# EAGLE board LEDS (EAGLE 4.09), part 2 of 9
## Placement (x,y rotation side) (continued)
LED12.81  LED_CROSS1/2  [LED_603]  33.11,22.47 180 top
LED12.82  LED_CROSS1/2  [LED_603]  34.92,22.47 180 top
LED12.83  LED_CROSS1/2  [LED_603]  36.72,22.47 180 top
LED12.84  LED_CROSS1/2  [LED_603]  38.53,22.47 180 top
LED12.85  LED_CROSS1/2  [LED_603]  40.33,22.47 180 top
LED12.86  LED_CROSS1/2  [LED_603]  42.12,22.47 180 top
LED12.87  LED_CROSS1/2  [LED_603]  43.92,22.47 180 top
LED12.88  LED_CROSS1/2  [LED_603]  45.71,22.47 180 top
LED12.89  LED_CROSS1/2  [LED_603]  47.5,22.47 180 top
LED12.90  LED_CROSS1/2  [LED_603]  49.3,22.47 180 top
LED12.91  LED_CROSS1/2  [LED_603]  51.12,22.47 180 top
LED12.92  LED_CROSS1/2  [LED_603]  52.91,22.47 180 top
LED12.93  LED_CROSS1/2  [LED_603]  54.71,22.47 180 top
LED12.94  LED_CROSS1/2  [LED_603]  56.51,22.47 180 top
LED12.95  LED_CROSS1/2  [LED_603]  58.31,22.47 180 top
LED12.98  LED_CROSS1/2  [LED_603]  61.93,22.47 180 top
LED12.99  LED_CROSS1/2  [LED_603]  63.68,22.47 180 top
LED12.100  LED_CROSS1/2  [LED_603]  65.5,22.47 180 top
LED12.101  LED_CROSS1/2  [LED_603]  67.41,22.47 180 top
LED12.102  LED_CROSS1/2  [LED_603]  69.16,22.47 180 top
LED12.103  LED_CROSS1/2  [LED_603]  70.88,22.47 180 top
LED12.104  LED_CROSS1/2  [LED_603]  72.68,22.47 180 top
LED12.105  LED_CROSS1/2  [LED_603]  74.41,22.47 180 top
LED12.106  LED_CROSS1/2  [LED_603]  76.18,22.47 180 top
LED12.107  LED_CROSS1/2  [LED_603]  77.91,22.47 180 top
LED12.108  LED_CROSS1/2  [LED_603]  79.66,22.47 180 top
LED12.109  LED_CROSS1/2  [LED_603]  81.48,22.47 180 top
LED12.110  LED_CROSS1/2  [LED_603]  83.16,22.47 180 top
LED12.111  LED_CROSS1/2  [LED_603]  84.91,22.47 180 top
LED12.112  LED_CROSS1/2  [LED_603]  86.68,22.47 180 top
LED12.113  LED_CROSS1/2  [LED_603]  88.34,22.47 180 top
LED12.114  LED_CROSS1/2  [LED_603]  90.16,22.47 180 top
LED12.115  LED_CROSS1/2  [LED_603]  91.98,22.47 180 top
LED12.116  LED_CROSS1/2  [LED_603]  93.78,22.47 180 top
LED12.117  LED_CROSS1/2  [LED_603]  95.45,22.47 180 top
LED12.118  LED_CROSS1/2  [LED_603]  97.18,22.47 180 top
LED12.119  LED_CROSS1/2  [LED_603]  98.91,22.47 180 top
LED12.120  LED_CROSS1/2  [LED_603]  100.66,22.47 180 top
LED12.121  LED_CROSS1/2  [LED_603]  102.38,22.47 180 top
LED12.122  LED_CROSS1/2  [LED_603]  104.16,22.47 180 top
LED12.123  LED_CROSS1/2  [LED_603]  105.91,22.47 180 top
LED12.124  LED_CROSS1/2  [LED_603]  107.61,22.47 180 top
LED12.125  LED_CROSS1/2  [LED_603]  109.38,22.44 180 top
LED12.126  LED_CROSS1/2  [LED_603]  111.08,22.44 180 top
LED12.127  LED_CROSS1/2  [LED_603]  112.86,22.44 180 top
LED13.0  LED_CROSS1/2  [LED_603]  2.57,48.74 180 top
LED13.1  LED_CROSS1/2  [LED_603]  4.37,48.74 180 top
LED13.2  LED_CROSS1/2  [LED_603]  6.18,48.74 180 top
LED13.3  LED_CROSS1/2  [LED_603]  7.97,48.75 180 top
LED13.4  LED_CROSS1/2  [LED_603]  9.72,48.74 180 top
LED13.5  LED_CROSS1/2  [LED_603]  11.52,48.74 180 top
LED13.6  LED_CROSS1/2  [LED_603]  13.32,48.74 180 top
LED13.7  LED_CROSS1/2  [LED_603]  15.12,48.74 180 top
LED13.8  LED_CROSS1/2  [LED_603]  16.92,48.74 180 top
LED13.9  LED_CROSS1/2  [LED_603]  18.72,48.74 180 top
LED13.10  LED_CROSS1/2  [LED_603]  20.52,48.75 180 top
LED13.11  LED_CROSS1/2  [LED_603]  22.32,48.75 180 top
LED13.12  LED_CROSS1/2  [LED_603]  24.12,48.75 180 top
LED13.13  LED_CROSS1/2  [LED_603]  25.91,48.75 180 top
LED13.14  LED_CROSS1/2  [LED_603]  27.72,48.75 180 top
LED13.15  LED_CROSS1/2  [LED_603]  29.52,48.75 180 top
LED13.16  LED_CROSS1/2  [LED_603]  31.32,48.75 180 top
LED13.17  LED_CROSS1/2  [LED_603]  33.13,48.75 180 top
LED13.18  LED_CROSS1/2  [LED_603]  34.93,48.75 180 top
LED13.19  LED_CROSS1/2  [LED_603]  36.72,48.75 180 top
LED13.20  LED_CROSS1/2  [LED_603]  38.51,48.75 180 top
LED13.21  LED_CROSS1/2  [LED_603]  40.33,48.74 180 top
LED13.22  LED_CROSS1/2  [LED_603]  42.12,48.74 180 top
LED13.23  LED_CROSS1/2  [LED_603]  43.91,48.74 180 top
LED13.24  LED_CROSS1/2  [LED_603]  45.71,48.74 180 top
LED13.25  LED_CROSS1/2  [LED_603]  47.51,48.74 180 top
LED13.26  LED_CROSS1/2  [LED_603]  49.3,48.74 180 top
LED13.27  LED_CROSS1/2  [LED_603]  51.12,48.74 180 top
LED13.28  LED_CROSS1/2  [LED_603]  52.91,48.74 180 top
LED13.29  LED_CROSS1/2  [LED_603]  54.71,48.74 180 top
LED13.30  LED_CROSS1/2  [LED_603]  56.5,48.74 180 top
LED13.31  LED_CROSS1/2  [LED_603]  58.3,48.74 180 top
LED13.32  LED_CROSS1/2  [LED_603]  60.11,48.74 180 top
LED13.34  LED_CROSS1/2  [LED_603]  61.92,48.74 180 top
LED13.35  LED_CROSS1/2  [LED_603]  63.69,48.74 180 top
LED13.36  LED_CROSS1/2  [LED_603]  65.46,48.74 180 top
LED13.37  LED_CROSS1/2  [LED_603]  67.3,48.74 180 top
LED13.38  LED_CROSS1/2  [LED_603]  69.08,48.74 180 top
LED13.39  LED_CROSS1/2  [LED_603]  70.88,48.74 180 top
LED13.40  LED_CROSS1/2  [LED_603]  72.63,48.74 180 top
LED13.41  LED_CROSS1/2  [LED_603]  74.36,48.74 180 top
LED13.42  LED_CROSS1/2  [LED_603]  76.08,48.74 180 top
LED13.43  LED_CROSS1/2  [LED_603]  77.86,48.74 180 top
LED13.44  LED_CROSS1/2  [LED_603]  79.61,48.74 180 top
LED13.45  LED_CROSS1/2  [LED_603]  81.36,48.74 180 top
LED13.46  LED_CROSS1/2  [LED_603]  83.16,48.74 180 top
LED13.47  LED_CROSS1/2  [LED_603]  84.91,48.74 180 top
LED13.48  LED_CROSS1/2  [LED_603]  86.63,48.74 180 top
LED13.49  LED_CROSS1/2  [LED_603]  88.41,48.74 180 top
LED13.50  LED_CROSS1/2  [LED_603]  90.16,48.72 180 top
LED13.51  LED_CROSS1/2  [LED_603]  91.93,48.72 180 top
LED13.52  LED_CROSS1/2  [LED_603]  93.68,48.72 180 top
LED13.53  LED_CROSS1/2  [LED_603]  95.43,48.72 180 top
LED13.54  LED_CROSS1/2  [LED_603]  97.16,48.72 180 top
LED13.55  LED_CROSS1/2  [LED_603]  98.88,48.72 180 top
LED13.56  LED_CROSS1/2  [LED_603]  100.66,48.72 180 top
LED13.57  LED_CROSS1/2  [LED_603]  102.38,48.72 180 top
LED13.58  LED_CROSS1/2  [LED_603]  104.16,48.72 180 top
LED13.59  LED_CROSS1/2  [LED_603]  105.91,48.72 180 top
LED13.60  LED_CROSS1/2  [LED_603]  107.61,48.72 180 top
LED13.61  LED_CROSS1/2  [LED_603]  109.38,48.72 180 top
LED13.62  LED_CROSS1/2  [LED_603]  111.11,48.72 180 top
LED13.63  LED_CROSS1/2  [LED_603]  112.88,48.72 180 top
LED13.64  LED_CROSS1/2  [LED_603]  2.57,19.89 180 top
LED13.65  LED_CROSS1/2  [LED_603]  4.37,19.89 180 top
LED13.66  LED_CROSS1/2  [LED_603]  6.17,19.89 180 top
LED13.67  LED_CROSS1/2  [LED_603]  7.97,19.89 180 top
LED13.68  LED_CROSS1/2  [LED_603]  9.73,19.89 180 top
LED13.69  LED_CROSS1/2  [LED_603]  11.52,19.89 180 top
LED13.70  LED_CROSS1/2  [LED_603]  13.32,19.89 180 top
LED13.71  LED_CROSS1/2  [LED_603]  15.12,19.88 180 top
LED13.72  LED_CROSS1/2  [LED_603]  16.92,19.88 180 top
LED13.73  LED_CROSS1/2  [LED_603]  18.72,19.89 180 top
LED13.74  LED_CROSS1/2  [LED_603]  20.52,19.88 180 top
LED13.75  LED_CROSS1/2  [LED_603]  22.32,19.89 180 top
LED13.76  LED_CROSS1/2  [LED_603]  24.12,19.89 180 top
LED13.77  LED_CROSS1/2  [LED_603]  25.92,19.88 180 top
LED13.78  LED_CROSS1/2  [LED_603]  27.72,19.88 180 top
LED13.79  LED_CROSS1/2  [LED_603]  29.52,19.88 180 top
LED13.80  LED_CROSS1/2  [LED_603]  31.32,19.89 180 top
LED13.81  LED_CROSS1/2  [LED_603]  33.13,19.89 180 top
LED13.82  LED_CROSS1/2  [LED_603]  34.92,19.89 180 top
LED13.83  LED_CROSS1/2  [LED_603]  36.72,19.89 180 top
LED13.84  LED_CROSS1/2  [LED_603]  38.51,19.89 180 top
LED13.85  LED_CROSS1/2  [LED_603]  40.32,19.89 180 top
LED13.86  LED_CROSS1/2  [LED_603]  42.12,19.89 180 top
LED13.87  LED_CROSS1/2  [LED_603]  43.92,19.89 180 top
LED13.88  LED_CROSS1/2  [LED_603]  45.71,19.89 180 top
LED13.89  LED_CROSS1/2  [LED_603]  47.51,19.89 180 top
LED13.90  LED_CROSS1/2  [LED_603]  49.3,19.89 180 top
LED13.91  LED_CROSS1/2  [LED_603]  51.12,19.89 180 top
LED13.92  LED_CROSS1/2  [LED_603]  52.91,19.89 180 top
LED13.93  LED_CROSS1/2  [LED_603]  54.71,19.89 180 top
LED13.94  LED_CROSS1/2  [LED_603]  56.5,19.89 180 top
LED13.95  LED_CROSS1/2  [LED_603]  58.3,19.89 180 top
LED13.96  LED_CROSS1/2  [LED_603]  61.89,17.32 180 top
LED13.97  LED_CROSS1/2  [LED_603]  60.12,19.89 180 top
LED13.98  LED_CROSS1/2  [LED_603]  61.92,19.89 180 top
LED13.99  LED_CROSS1/2  [LED_603]  63.68,19.89 180 top
LED13.100  LED_CROSS1/2  [LED_603]  65.46,19.89 180 top
LED13.101  LED_CROSS1/2  [LED_603]  67.11,19.89 180 top
LED13.102  LED_CROSS1/2  [LED_603]  68.88,19.89 180 top
LED13.103  LED_CROSS1/2  [LED_603]  70.68,19.89 180 top
LED13.104  LED_CROSS1/2  [LED_603]  72.43,19.89 180 top
LED13.105  LED_CROSS1/2  [LED_603]  74.16,19.89 180 top
LED13.106  LED_CROSS1/2  [LED_603]  75.88,19.89 180 top
LED13.107  LED_CROSS1/2  [LED_603]  77.66,19.89 180 top
LED13.108  LED_CROSS1/2  [LED_603]  79.41,19.89 180 top
LED13.109  LED_CROSS1/2  [LED_603]  81.16,19.89 180 top
LED13.110  LED_CROSS1/2  [LED_603]  82.95,19.89 180 top
LED13.111  LED_CROSS1/2  [LED_603]  84.91,19.89 180 top
LED13.112  LED_CROSS1/2  [LED_603]  86.68,19.89 180 top
LED13.113  LED_CROSS1/2  [LED_603]  88.44,19.87 180 top
LED13.114  LED_CROSS1/2  [LED_603]  90.16,19.87 180 top
LED13.115  LED_CROSS1/2  [LED_603]  91.98,19.87 180 top
LED13.116  LED_CROSS1/2  [LED_603]  93.78,19.87 180 top
LED13.117  LED_CROSS1/2  [LED_603]  95.43,19.87 180 top
LED13.118  LED_CROSS1/2  [LED_603]  97.16,19.87 180 top
LED13.119  LED_CROSS1/2  [LED_603]  98.93,19.87 180 top
LED13.120  LED_CROSS1/2  [LED_603]  100.7,19.87 180 top
LED13.121  LED_CROSS1/2  [LED_603]  102.38,19.87 180 top
LED13.122  LED_CROSS1/2  [LED_603]  104.16,19.87 180 top
LED13.123  LED_CROSS1/2  [LED_603]  105.95,19.87 180 top
LED13.124  LED_CROSS1/2  [LED_603]  107.61,19.87 180 top
LED13.125  LED_CROSS1/2  [LED_603]  109.38,19.87 180 top
LED13.126  LED_CROSS1/2  [LED_603]  111.05,19.87 180 top
LED13.127  LED_CROSS1/2  [LED_603]  112.88,19.87 180 top
LED14.0  LED_CROSS1/2  [LED_603]  2.57,46.17 180 top
LED14.1  LED_CROSS1/2  [LED_603]  4.37,46.17 180 top
LED14.2  LED_CROSS1/2  [LED_603]  6.18,46.17 180 top
LED14.3  LED_CROSS1/2  [LED_603]  7.96,46.17 180 top
LED14.4  LED_CROSS1/2  [LED_603]  9.72,46.17 180 top
LED14.5  LED_CROSS1/2  [LED_603]  11.52,46.17 180 top
LED14.6  LED_CROSS1/2  [LED_603]  13.32,46.17 180 top
LED14.7  LED_CROSS1/2  [LED_603]  15.12,46.17 180 top
LED14.8  LED_CROSS1/2  [LED_603]  16.92,46.17 180 top
LED14.9  LED_CROSS1/2  [LED_603]  18.72,46.17 180 top
LED14.10  LED_CROSS1/2  [LED_603]  20.51,46.17 180 top
LED14.11  LED_CROSS1/2  [LED_603]  22.32,46.17 180 top
LED14.12  LED_CROSS1/2  [LED_603]  24.12,46.17 180 top
LED14.13  LED_CROSS1/2  [LED_603]  25.92,46.17 180 top
LED14.14  LED_CROSS1/2  [LED_603]  27.72,46.16 180 top
LED14.15  LED_CROSS1/2  [LED_603]  29.52,46.17 180 top
LED14.16  LED_CROSS1/2  [LED_603]  31.32,46.17 180 top
LED14.17  LED_CROSS1/2  [LED_603]  33.13,46.17 180 top
LED14.18  LED_CROSS1/2  [LED_603]  34.93,46.17 180 top
LED14.19  LED_CROSS1/2  [LED_603]  36.73,46.17 180 top
LED14.20  LED_CROSS1/2  [LED_603]  38.51,46.17 180 top
LED14.21  LED_CROSS1/2  [LED_603]  40.33,46.17 180 top
LED14.22  LED_CROSS1/2  [LED_603]  42.12,46.17 180 top
LED14.23  LED_CROSS1/2  [LED_603]  43.91,46.17 180 top
LED14.24  LED_CROSS1/2  [LED_603]  45.71,46.17 180 top
LED14.25  LED_CROSS1/2  [LED_603]  47.5,46.17 180 top
LED14.26  LED_CROSS1/2  [LED_603]  49.3,46.17 180 top
LED14.27  LED_CROSS1/2  [LED_603]  51.12,46.17 180 top
LED14.28  LED_CROSS1/2  [LED_603]  52.91,46.17 180 top
LED14.29  LED_CROSS1/2  [LED_603]  54.71,46.17 180 top
LED14.30  LED_CROSS1/2  [LED_603]  56.5,46.17 180 top
LED14.31  LED_CROSS1/2  [LED_603]  58.3,46.17 180 top
LED14.32  LED_CROSS1/2  [LED_603]  60.09,46.17 180 top
LED14.33  LED_CROSS1/2  [LED_603]  113,82.68 180 top
LED14.34  LED_CROSS1/2  [LED_603]  61.92,46.15 180 top
LED14.35  LED_CROSS1/2  [LED_603]  63.69,46.15 180 top
LED14.36  LED_CROSS1/2  [LED_603]  65.46,46.15 180 top
LED14.37  LED_CROSS1/2  [LED_603]  67.33,46.19 180 top
LED14.38  LED_CROSS1/2  [LED_603]  69.11,46.19 180 top
LED14.39  LED_CROSS1/2  [LED_603]  70.88,46.19 180 top
LED14.40  LED_CROSS1/2  [LED_603]  72.63,46.19 180 top
LED14.41  LED_CROSS1/2  [LED_603]  74.36,46.19 180 top
LED14.42  LED_CROSS1/2  [LED_603]  76.11,46.19 180 top
LED14.43  LED_CROSS1/2  [LED_603]  77.88,46.19 180 top
LED14.44  LED_CROSS1/2  [LED_603]  79.61,46.19 180 top
LED14.45  LED_CROSS1/2  [LED_603]  81.38,46.19 180 top
LED14.46  LED_CROSS1/2  [LED_603]  83.16,46.19 180 top
LED14.47  LED_CROSS1/2  [LED_603]  84.91,46.19 180 top
LED14.48  LED_CROSS1/2  [LED_603]  86.66,46.19 180 top
LED14.49  LED_CROSS1/2  [LED_603]  88.43,46.19 180 top
LED14.50  LED_CROSS1/2  [LED_603]  90.16,46.19 180 top
LED14.51  LED_CROSS1/2  [LED_603]  91.95,46.19 180 top
LED14.52  LED_CROSS1/2  [LED_603]  93.73,46.19 180 top
LED14.53  LED_CROSS1/2  [LED_603]  95.43,46.19 180 top
LED14.54  LED_CROSS1/2  [LED_603]  97.16,46.19 180 top
LED14.55  LED_CROSS1/2  [LED_603]  98.91,46.22 180 top
LED14.56  LED_CROSS1/2  [LED_603]  100.66,46.22 180 top
LED14.57  LED_CROSS1/2  [LED_603]  102.38,46.22 180 top
LED14.58  LED_CROSS1/2  [LED_603]  104.16,46.22 180 top
LED14.59  LED_CROSS1/2  [LED_603]  105.91,46.24 180 top
LED14.60  LED_CROSS1/2  [LED_603]  107.61,46.24 180 top
LED14.61  LED_CROSS1/2  [LED_603]  109.38,46.24 180 top
LED14.62  LED_CROSS1/2  [LED_603]  111.13,46.24 180 top
LED14.63  LED_CROSS1/2  [LED_603]  112.88,46.24 180 top
LED14.64  LED_CROSS1/2  [LED_603]  2.57,17.32 180 top
LED14.65  LED_CROSS1/2  [LED_603]  4.37,17.32 180 top
LED14.66  LED_CROSS1/2  [LED_603]  6.17,17.32 180 top
LED14.67  LED_CROSS1/2  [LED_603]  7.97,17.32 180 top
LED14.68  LED_CROSS1/2  [LED_603]  9.73,17.32 180 top
LED14.69  LED_CROSS1/2  [LED_603]  11.52,17.32 180 top
LED14.70  LED_CROSS1/2  [LED_603]  13.32,17.32 180 top
LED14.71  LED_CROSS1/2  [LED_603]  15.12,17.32 180 top
LED14.72  LED_CROSS1/2  [LED_603]  16.92,17.32 180 top
LED14.73  LED_CROSS1/2  [LED_603]  18.72,17.32 180 top
LED14.74  LED_CROSS1/2  [LED_603]  20.52,17.32 180 top
LED14.75  LED_CROSS1/2  [LED_603]  22.32,17.32 180 top
LED14.76  LED_CROSS1/2  [LED_603]  24.12,17.32 180 top
LED14.77  LED_CROSS1/2  [LED_603]  25.91,17.32 180 top
LED14.78  LED_CROSS1/2  [LED_603]  27.72,17.32 180 top
LED14.79  LED_CROSS1/2  [LED_603]  29.52,17.31 180 top
LED14.80  LED_CROSS1/2  [LED_603]  31.32,17.32 180 top
LED14.81  LED_CROSS1/2  [LED_603]  33.13,17.32 180 top
LED14.82  LED_CROSS1/2  [LED_603]  34.92,17.32 180 top
LED14.83  LED_CROSS1/2  [LED_603]  36.72,17.32 180 top
LED14.84  LED_CROSS1/2  [LED_603]  38.51,17.32 180 top
LED14.85  LED_CROSS1/2  [LED_603]  40.32,17.32 180 top
LED14.86  LED_CROSS1/2  [LED_603]  42.12,17.32 180 top
LED14.87  LED_CROSS1/2  [LED_603]  43.91,17.32 180 top
LED14.88  LED_CROSS1/2  [LED_603]  45.71,17.32 180 top
LED14.89  LED_CROSS1/2  [LED_603]  47.51,17.32 180 top
LED14.90  LED_CROSS1/2  [LED_603]  49.3,17.32 180 top
LED14.91  LED_CROSS1/2  [LED_603]  51.12,17.32 180 top
LED14.92  LED_CROSS1/2  [LED_603]  52.91,17.32 180 top
LED14.93  LED_CROSS1/2  [LED_603]  54.71,17.32 180 top
LED14.94  LED_CROSS1/2  [LED_603]  56.5,17.32 180 top
LED14.95  LED_CROSS1/2  [LED_603]  58.3,17.32 180 top
LED14.96  LED_CROSS1/2  [LED_603]  114.97,59.36 180 top
LED14.97  LED_CROSS1/2  [LED_603]  60.09,17.32 180 top
LED14.98  LED_CROSS1/2  [LED_603]  114.93,82.7 180 top
LED14.99  LED_CROSS1/2  [LED_603]  63.68,17.3 180 top
LED14.100  LED_CROSS1/2  [LED_603]  65.46,17.3 180 top
LED14.101  LED_CROSS1/2  [LED_603]  67.13,17.34 180 top
LED14.102  LED_CROSS1/2  [LED_603]  68.91,17.34 180 top
LED14.103  LED_CROSS1/2  [LED_603]  70.68,17.34 180 top
LED14.104  LED_CROSS1/2  [LED_603]  72.43,17.34 180 top
LED14.105  LED_CROSS1/2  [LED_603]  74.16,17.34 180 top
LED14.106  LED_CROSS1/2  [LED_603]  75.91,17.34 180 top
LED14.107  LED_CROSS1/2  [LED_603]  77.68,17.34 180 top
LED14.108  LED_CROSS1/2  [LED_603]  79.41,17.34 180 top
LED14.109  LED_CROSS1/2  [LED_603]  81.18,17.34 180 top
LED14.110  LED_CROSS1/2  [LED_603]  82.95,17.34 180 top
LED14.111  LED_CROSS1/2  [LED_603]  84.91,17.34 180 top
LED14.112  LED_CROSS1/2  [LED_603]  86.7,17.34 180 top
LED14.113  LED_CROSS1/2  [LED_603]  88.39,17.34 180 top
LED14.114  LED_CROSS1/2  [LED_603]  90.2,17.34 180 top
LED14.115  LED_CROSS1/2  [LED_603]  91.95,17.34 180 top
LED14.116  LED_CROSS1/2  [LED_603]  93.78,17.34 180 top
LED14.117  LED_CROSS1/2  [LED_603]  95.48,17.34 180 top
LED14.118  LED_CROSS1/2  [LED_603]  97.2,17.34 180 top
LED14.119  LED_CROSS1/2  [LED_603]  98.95,17.37 180 top
LED14.120  LED_CROSS1/2  [LED_603]  100.7,17.37 180 top
LED14.121  LED_CROSS1/2  [LED_603]  102.43,17.37 180 top
LED14.122  LED_CROSS1/2  [LED_603]  104.16,17.42 180 top
LED14.123  LED_CROSS1/2  [LED_603]  105.95,17.39 180 top
LED14.124  LED_CROSS1/2  [LED_603]  107.61,17.39 180 top
LED14.125  LED_CROSS1/2  [LED_603]  109.33,17.39 180 top
LED14.126  LED_CROSS1/2  [LED_603]  111.08,17.39 180 top
LED14.127  LED_CROSS1/2  [LED_603]  112.88,17.39 180 top
LED14.128  LED_CROSS1/2  [LED_603]  114.95,75.01 180 top
LED14.129  LED_CROSS1/2  [LED_603]  114.95,67.19 180 top
LED14.130  LED_CROSS1/2  [LED_603]  114.96,48.71 180 top
LED14.131  LED_CROSS1/2  [LED_603]  114.98,43.65 180 top
LED14.132  LED_CROSS1/2  [LED_603]  114.98,38.5 180 top
LED14.133  LED_CROSS1/2  [LED_603]  114.93,33.2 180 top
LED15.0  LED_CROSS1/2  [LED_603]  2.57,43.64 180 top
LED15.1  LED_CROSS1/2  [LED_603]  4.37,43.64 180 top
LED15.2  LED_CROSS1/2  [LED_603]  6.18,43.64 180 top
LED15.3  LED_CROSS1/2  [LED_603]  7.97,43.64 180 top
LED15.4  LED_CROSS1/2  [LED_603]  9.72,43.64 180 top
LED15.5  LED_CROSS1/2  [LED_603]  11.52,43.64 180 top
LED15.6  LED_CROSS1/2  [LED_603]  13.33,43.64 180 top
LED15.7  LED_CROSS1/2  [LED_603]  15.12,43.63 180 top
LED15.8  LED_CROSS1/2  [LED_603]  16.93,43.63 180 top
LED15.9  LED_CROSS1/2  [LED_603]  18.72,43.63 180 top
LED15.10  LED_CROSS1/2  [LED_603]  20.52,43.63 180 top
LED15.11  LED_CROSS1/2  [LED_603]  22.32,43.64 180 top
LED15.12  LED_CROSS1/2  [LED_603]  24.12,43.63 180 top
LED15.13  LED_CROSS1/2  [LED_603]  25.92,43.64 180 top
LED15.14  LED_CROSS1/2  [LED_603]  27.72,43.64 180 top
LED15.15  LED_CROSS1/2  [LED_603]  29.51,43.63 180 top
LED15.16  LED_CROSS1/2  [LED_603]  31.31,43.64 180 top
LED15.17  LED_CROSS1/2  [LED_603]  33.13,43.64 180 top
LED15.18  LED_CROSS1/2  [LED_603]  34.93,43.64 180 top
LED15.19  LED_CROSS1/2  [LED_603]  36.73,43.64 180 top
LED15.20  LED_CROSS1/2  [LED_603]  38.51,43.64 180 top
LED15.21  LED_CROSS1/2  [LED_603]  40.33,43.64 180 top
LED15.22  LED_CROSS1/2  [LED_603]  42.12,43.64 180 top
LED15.23  LED_CROSS1/2  [LED_603]  43.91,43.64 180 top
LED15.24  LED_CROSS1/2  [LED_603]  45.71,43.64 180 top
LED15.25  LED_CROSS1/2  [LED_603]  47.5,43.64 180 top
LED15.26  LED_CROSS1/2  [LED_603]  49.3,43.64 180 top
LED15.27  LED_CROSS1/2  [LED_603]  51.12,43.64 180 top
LED15.28  LED_CROSS1/2  [LED_603]  52.91,43.64 180 top
LED15.29  LED_CROSS1/2  [LED_603]  54.71,43.64 180 top
LED15.30  LED_CROSS1/2  [LED_603]  56.5,43.64 180 top
LED15.31  LED_CROSS1/2  [LED_603]  58.3,43.64 180 top
LED15.32  LED_CROSS1/2  [LED_603]  60.09,43.64 180 top
LED15.34  LED_CROSS1/2  [LED_603]  61.92,43.6 180 top
LED15.35  LED_CROSS1/2  [LED_603]  63.71,43.6 180 top
LED15.36  LED_CROSS1/2  [LED_603]  65.46,43.6 180 top
LED15.37  LED_CROSS1/2  [LED_603]  67.33,43.64 180 top
LED15.38  LED_CROSS1/2  [LED_603]  69.13,43.64 180 top
LED15.39  LED_CROSS1/2  [LED_603]  70.88,43.64 180 top
LED15.40  LED_CROSS1/2  [LED_603]  72.63,43.64 180 top
LED15.41  LED_CROSS1/2  [LED_603]  74.36,43.64 180 top
LED15.42  LED_CROSS1/2  [LED_603]  76.11,43.64 180 top
LED15.43  LED_CROSS1/2  [LED_603]  77.88,43.64 180 top
LED15.44  LED_CROSS1/2  [LED_603]  79.66,43.64 180 top
LED15.45  LED_CROSS1/2  [LED_603]  81.41,43.64 180 top
LED15.46  LED_CROSS1/2  [LED_603]  83.18,43.64 180 top
LED15.47  LED_CROSS1/2  [LED_603]  84.93,43.64 180 top
LED15.48  LED_CROSS1/2  [LED_603]  86.66,43.64 180 top
LED15.49  LED_CROSS1/2  [LED_603]  88.43,43.64 180 top
LED15.50  LED_CROSS1/2  [LED_603]  90.16,43.64 180 top
LED15.51  LED_CROSS1/2  [LED_603]  91.95,43.64 180 top
LED15.52  LED_CROSS1/2  [LED_603]  93.73,43.64 180 top
LED15.53  LED_CROSS1/2  [LED_603]  95.45,43.64 180 top
LED15.54  LED_CROSS1/2  [LED_603]  97.16,43.64 180 top
LED15.55  LED_CROSS1/2  [LED_603]  98.93,43.64 180 top
LED15.56  LED_CROSS1/2  [LED_603]  100.68,43.67 180 top
LED15.57  LED_CROSS1/2  [LED_603]  102.38,43.67 180 top
LED15.58  LED_CROSS1/2  [LED_603]  104.16,43.67 180 top
LED15.59  LED_CROSS1/2  [LED_603]  105.91,43.67 180 top
LED15.60  LED_CROSS1/2  [LED_603]  107.61,43.67 180 top
LED15.61  LED_CROSS1/2  [LED_603]  109.38,43.67 180 top
LED15.62  LED_CROSS1/2  [LED_603]  111.11,43.67 180 top
LED15.63  LED_CROSS1/2  [LED_603]  112.88,43.67 180 top
LED15.64  LED_CROSS1/2  [LED_603]  2.57,14.8 180 top
LED15.65  LED_CROSS1/2  [LED_603]  4.37,14.8 180 top
LED15.66  LED_CROSS1/2  [LED_603]  6.18,14.8 180 top
LED15.67  LED_CROSS1/2  [LED_603]  7.96,14.81 180 top
LED15.68  LED_CROSS1/2  [LED_603]  9.73,14.8 180 top
LED15.69  LED_CROSS1/2  [LED_603]  11.53,14.79 180 top
LED15.70  LED_CROSS1/2  [LED_603]  13.32,14.79 180 top
LED15.71  LED_CROSS1/2  [LED_603]  15.12,14.79 180 top
LED15.72  LED_CROSS1/2  [LED_603]  16.91,14.79 180 top
LED15.73  LED_CROSS1/2  [LED_603]  18.72,14.8 180 top
LED15.74  LED_CROSS1/2  [LED_603]  20.52,14.79 180 top
LED15.75  LED_CROSS1/2  [LED_603]  22.32,14.79 180 top
LED15.76  LED_CROSS1/2  [LED_603]  24.12,14.79 180 top
LED15.77  LED_CROSS1/2  [LED_603]  25.92,14.79 180 top
LED15.78  LED_CROSS1/2  [LED_603]  27.71,14.79 180 top
LED15.79  LED_CROSS1/2  [LED_603]  29.52,14.79 180 top
LED15.80  LED_CROSS1/2  [LED_603]  31.31,14.79 180 top
LED15.81  LED_CROSS1/2  [LED_603]  33.13,14.79 180 top
LED15.82  LED_CROSS1/2  [LED_603]  34.92,14.79 180 top
LED15.83  LED_CROSS1/2  [LED_603]  36.72,14.79 180 top
LED15.84  LED_CROSS1/2  [LED_603]  38.51,14.79 180 top
LED15.85  LED_CROSS1/2  [LED_603]  40.32,14.79 180 top
LED15.86  LED_CROSS1/2  [LED_603]  42.12,14.79 180 top
LED15.87  LED_CROSS1/2  [LED_603]  43.91,14.79 180 top
LED15.88  LED_CROSS1/2  [LED_603]  45.71,14.79 180 top
LED15.89  LED_CROSS1/2  [LED_603]  47.51,14.79 180 top
LED15.90  LED_CROSS1/2  [LED_603]  49.3,14.79 180 top
LED15.91  LED_CROSS1/2  [LED_603]  51.12,14.79 180 top
LED15.92  LED_CROSS1/2  [LED_603]  52.91,14.79 180 top
LED15.93  LED_CROSS1/2  [LED_603]  54.71,14.79 180 top
LED15.94  LED_CROSS1/2  [LED_603]  56.5,14.79 180 top
LED15.95  LED_CROSS1/2  [LED_603]  58.32,14.79 180 top
LED15.97  LED_CROSS1/2  [LED_603]  60.1,14.77 180 top
LED15.98  LED_CROSS1/2  [LED_603]  61.92,14.79 180 top
LED15.99  LED_CROSS1/2  [LED_603]  63.71,14.79 180 top
LED15.100  LED_CROSS1/2  [LED_603]  65.46,14.79 180 top
LED15.101  LED_CROSS1/2  [LED_603]  67.13,14.79 180 top
LED15.102  LED_CROSS1/2  [LED_603]  68.93,14.79 180 top
LED15.103  LED_CROSS1/2  [LED_603]  70.68,14.79 180 top
LED15.104  LED_CROSS1/2  [LED_603]  72.43,14.79 180 top
LED15.105  LED_CROSS1/2  [LED_603]  74.16,14.79 180 top
LED15.106  LED_CROSS1/2  [LED_603]  75.91,14.79 180 top
LED15.107  LED_CROSS1/2  [LED_603]  77.68,14.79 180 top
LED15.108  LED_CROSS1/2  [LED_603]  79.45,14.79 180 top
LED15.109  LED_CROSS1/2  [LED_603]  81.2,14.79 180 top
LED15.110  LED_CROSS1/2  [LED_603]  82.98,14.79 180 top
LED15.111  LED_CROSS1/2  [LED_603]  84.93,14.79 180 top
LED15.112  LED_CROSS1/2  [LED_603]  86.7,14.79 180 top
LED15.113  LED_CROSS1/2  [LED_603]  88.45,14.79 180 top
LED15.114  LED_CROSS1/2  [LED_603]  90.2,14.79 180 top
LED15.115  LED_CROSS1/2  [LED_603]  91.95,14.79 180 top
LED15.116  LED_CROSS1/2  [LED_603]  93.78,14.79 180 top
LED15.117  LED_CROSS1/2  [LED_603]  95.45,14.79 180 top
LED15.118  LED_CROSS1/2  [LED_603]  97.25,14.79 180 top
LED15.119  LED_CROSS1/2  [LED_603]  98.98,14.79 180 top
LED15.120  LED_CROSS1/2  [LED_603]  100.73,14.82 180 top
LED15.121  LED_CROSS1/2  [LED_603]  102.43,14.82 180 top
LED15.122  LED_CROSS1/2  [LED_603]  104.16,14.82 180 top
LED15.123  LED_CROSS1/2  [LED_603]  105.95,14.82 180 top
LED15.124  LED_CROSS1/2  [LED_603]  107.61,14.82 180 top
LED15.125  LED_CROSS1/2  [LED_603]  109.33,14.82 180 top
LED15.126  LED_CROSS1/2  [LED_603]  111.11,14.82 180 top
LED15.127  LED_CROSS1/2  [LED_603]  112.88,14.82 180 top
LED16.0  LED_CROSS1/2  [LED_603]  2.57,41.04 180 top
LED16.1  LED_CROSS1/2  [LED_603]  4.37,41.04 180 top
LED16.2  LED_CROSS1/2  [LED_603]  6.18,41.04 180 top
LED16.3  LED_CROSS1/2  [LED_603]  7.97,41.04 180 top
LED16.4  LED_CROSS1/2  [LED_603]  9.72,41.04 180 top
LED16.5  LED_CROSS1/2  [LED_603]  11.52,41.04 180 top
LED16.6  LED_CROSS1/2  [LED_603]  13.33,41.04 180 top
LED16.7  LED_CROSS1/2  [LED_603]  15.12,41.03 180 top
LED16.8  LED_CROSS1/2  [LED_603]  16.92,41.03 180 top
LED16.9  LED_CROSS1/2  [LED_603]  18.72,41.03 180 top
LED16.10  LED_CROSS1/2  [LED_603]  20.52,41.03 180 top
LED16.11  LED_CROSS1/2  [LED_603]  22.32,41.03 180 top
LED16.12  LED_CROSS1/2  [LED_603]  24.12,41.03 180 top
LED16.13  LED_CROSS1/2  [LED_603]  25.92,41.03 180 top
LED16.14  LED_CROSS1/2  [LED_603]  27.72,41.03 180 top
LED16.15  LED_CROSS1/2  [LED_603]  29.52,41.03 180 top
LED16.16  LED_CROSS1/2  [LED_603]  31.32,41.04 180 top
LED16.17  LED_CROSS1/2  [LED_603]  33.13,41.04 180 top
LED16.18  LED_CROSS1/2  [LED_603]  34.93,41.04 180 top
LED16.19  LED_CROSS1/2  [LED_603]  36.72,41.04 180 top
LED16.20  LED_CROSS1/2  [LED_603]  38.51,41.04 180 top
LED16.21  LED_CROSS1/2  [LED_603]  40.33,41.02 180 top
LED16.22  LED_CROSS1/2  [LED_603]  42.12,41.02 180 top
LED16.23  LED_CROSS1/2  [LED_603]  43.91,41.02 180 top
LED16.24  LED_CROSS1/2  [LED_603]  45.71,41.02 180 top
LED16.25  LED_CROSS1/2  [LED_603]  47.5,41.02 180 top
LED16.26  LED_CROSS1/2  [LED_603]  49.3,41.02 180 top
LED16.27  LED_CROSS1/2  [LED_603]  51.12,41.02 180 top
LED16.28  LED_CROSS1/2  [LED_603]  52.91,41.02 180 top
LED16.29  LED_CROSS1/2  [LED_603]  54.71,41.02 180 top
LED16.30  LED_CROSS1/2  [LED_603]  56.5,41.02 180 top
LED16.31  LED_CROSS1/2  [LED_603]  58.3,41.02 180 top
LED16.33  LED_CROSS1/2  [LED_603]  60.1,41.02 180 top
LED16.34  LED_CROSS1/2  [LED_603]  61.89,41.02 180 top
LED16.35  LED_CROSS1/2  [LED_603]  63.7,41.02 180 top
LED16.36  LED_CROSS1/2  [LED_603]  65.49,41.02 180 top
LED16.37  LED_CROSS1/2  [LED_603]  67.38,41.04 180 top
LED16.38  LED_CROSS1/2  [LED_603]  69.16,41.04 180 top
LED16.39  LED_CROSS1/2  [LED_603]  70.88,41.04 180 top
LED16.40  LED_CROSS1/2  [LED_603]  72.66,41.04 180 top
LED16.41  LED_CROSS1/2  [LED_603]  74.36,41.04 180 top
LED16.42  LED_CROSS1/2  [LED_603]  76.11,41.04 180 top
LED16.43  LED_CROSS1/2  [LED_603]  77.91,41.04 180 top
LED16.44  LED_CROSS1/2  [LED_603]  79.66,41.04 180 top
LED16.45  LED_CROSS1/2  [LED_603]  81.43,41.04 180 top
LED16.46  LED_CROSS1/2  [LED_603]  83.18,41.04 180 top
LED16.47  LED_CROSS1/2  [LED_603]  84.93,41.04 180 top
LED16.48  LED_CROSS1/2  [LED_603]  86.68,41.04 180 top
LED16.49  LED_CROSS1/2  [LED_603]  88.43,41.04 180 top
LED16.50  LED_CROSS1/2  [LED_603]  90.16,41.04 180 top
LED16.51  LED_CROSS1/2  [LED_603]  91.95,41.04 180 top
LED16.52  LED_CROSS1/2  [LED_603]  93.7,41.07 180 top
LED16.53  LED_CROSS1/2  [LED_603]  95.45,41.07 180 top
LED16.54  LED_CROSS1/2  [LED_603]  97.2,41.07 180 top
LED16.55  LED_CROSS1/2  [LED_603]  98.98,41.07 180 top
LED16.56  LED_CROSS1/2  [LED_603]  100.68,41.07 180 top
LED16.57  LED_CROSS1/2  [LED_603]  102.41,41.07 180 top
LED16.58  LED_CROSS1/2  [LED_603]  104.16,41.07 180 top
LED16.59  LED_CROSS1/2  [LED_603]  105.91,41.07 180 top
LED16.60  LED_CROSS1/2  [LED_603]  107.61,41.07 180 top
LED16.61  LED_CROSS1/2  [LED_603]  109.38,41.07 180 top
LED16.62  LED_CROSS1/2  [LED_603]  111.11,41.07 180 top
LED16.63  LED_CROSS1/2  [LED_603]  112.88,41.07 180 top
LED16.64  LED_CROSS1/2  [LED_603]  2.57,12.18 180 top
LED16.65  LED_CROSS1/2  [LED_603]  4.37,12.18 180 top
LED16.66  LED_CROSS1/2  [LED_603]  6.18,12.18 180 top
LED16.67  LED_CROSS1/2  [LED_603]  7.96,12.18 180 top
LED16.68  LED_CROSS1/2  [LED_603]  9.73,12.18 180 top
LED16.69  LED_CROSS1/2  [LED_603]  11.53,12.18 180 top
LED16.70  LED_CROSS1/2  [LED_603]  13.33,12.18 180 top
LED16.71  LED_CROSS1/2  [LED_603]  15.12,12.16 180 top
LED16.72  LED_CROSS1/2  [LED_603]  16.92,12.16 180 top
LED16.73  LED_CROSS1/2  [LED_603]  18.72,12.15 180 top
LED16.74  LED_CROSS1/2  [LED_603]  20.52,12.15 180 top
LED16.75  LED_CROSS1/2  [LED_603]  22.32,12.15 180 top
LED16.76  LED_CROSS1/2  [LED_603]  24.12,12.16 180 top
LED16.77  LED_CROSS1/2  [LED_603]  25.92,12.16 180 top
LED16.78  LED_CROSS1/2  [LED_603]  27.72,12.16 180 top
LED16.79  LED_CROSS1/2  [LED_603]  29.52,12.16 180 top
LED16.80  LED_CROSS1/2  [LED_603]  31.31,12.17 180 top
LED16.81  LED_CROSS1/2  [LED_603]  33.13,12.17 180 top
LED16.82  LED_CROSS1/2  [LED_603]  34.95,12.17 180 top
LED16.83  LED_CROSS1/2  [LED_603]  36.72,12.17 180 top
LED16.84  LED_CROSS1/2  [LED_603]  38.53,12.17 180 top
LED16.85  LED_CROSS1/2  [LED_603]  40.32,12.17 180 top
LED16.86  LED_CROSS1/2  [LED_603]  42.12,12.17 180 top
LED16.87  LED_CROSS1/2  [LED_603]  43.91,12.17 180 top
LED16.88  LED_CROSS1/2  [LED_603]  45.71,12.17 180 top
LED16.89  LED_CROSS1/2  [LED_603]  47.51,12.17 180 top
LED16.90  LED_CROSS1/2  [LED_603]  49.3,12.17 180 top
LED16.91  LED_CROSS1/2  [LED_603]  51.1,12.17 180 top
LED16.92  LED_CROSS1/2  [LED_603]  52.91,12.17 180 top
LED16.93  LED_CROSS1/2  [LED_603]  54.71,12.17 180 top
LED16.94  LED_CROSS1/2  [LED_603]  56.5,12.17 180 top
LED16.95  LED_CROSS1/2  [LED_603]  58.3,12.17 180 top
LED16.97  LED_CROSS1/2  [LED_603]  60.1,12.15 180 top
LED16.98  LED_CROSS1/2  [LED_603]  61.94,12.15 180 top
LED16.99  LED_CROSS1/2  [LED_603]  63.7,12.15 180 top
LED16.100  LED_CROSS1/2  [LED_603]  65.47,12.15 180 top
LED16.101  LED_CROSS1/2  [LED_603]  67.18,12.15 180 top
LED16.102  LED_CROSS1/2  [LED_603]  68.95,12.19 180 top
LED16.103  LED_CROSS1/2  [LED_603]  70.68,12.19 180 top
LED16.104  LED_CROSS1/2  [LED_603]  72.45,12.19 180 top
LED16.105  LED_CROSS1/2  [LED_603]  74.16,12.19 180 top
LED16.106  LED_CROSS1/2  [LED_603]  75.91,12.19 180 top
LED16.107  LED_CROSS1/2  [LED_603]  77.7,12.19 180 top
LED16.108  LED_CROSS1/2  [LED_603]  79.45,12.19 180 top
LED16.109  LED_CROSS1/2  [LED_603]  81.23,12.19 180 top
LED16.110  LED_CROSS1/2  [LED_603]  82.98,12.19 180 top
LED16.111  LED_CROSS1/2  [LED_603]  84.98,12.24 180 top
LED16.112  LED_CROSS1/2  [LED_603]  86.73,12.24 180 top
LED16.113  LED_CROSS1/2  [LED_603]  88.41,12.24 180 top
LED16.114  LED_CROSS1/2  [LED_603]  90.25,12.24 180 top
LED16.115  LED_CROSS1/2  [LED_603]  91.95,12.24 180 top
LED16.116  LED_CROSS1/2  [LED_603]  93.8,12.22 180 top
LED16.117  LED_CROSS1/2  [LED_603]  95.41,12.22 180 top
LED16.118  LED_CROSS1/2  [LED_603]  97.25,12.22 180 top
LED16.119  LED_CROSS1/2  [LED_603]  98.98,12.22 180 top
LED16.120  LED_CROSS1/2  [LED_603]  100.73,12.22 180 top
LED16.121  LED_CROSS1/2  [LED_603]  102.41,12.22 180 top
LED16.122  LED_CROSS1/2  [LED_603]  104.16,12.17 180 top
LED16.123  LED_CROSS1/2  [LED_603]  105.95,12.17 180 top
LED16.124  LED_CROSS1/2  [LED_603]  107.61,12.17 180 top
LED16.125  LED_CROSS1/2  [LED_603]  109.33,12.17 180 top
LED16.126  LED_CROSS1/2  [LED_603]  111.16,12.17 180 top
LED16.127  LED_CROSS1/2  [LED_603]  112.88,12.17 180 top
LED17.0  LED_CROSS1/2  [LED_603]  2.57,38.42 180 top
LED17.1  LED_CROSS1/2  [LED_603]  4.37,38.42 180 top
LED17.2  LED_CROSS1/2  [LED_603]  6.18,38.42 180 top
LED17.3  LED_CROSS1/2  [LED_603]  7.97,38.42 180 top
LED17.4  LED_CROSS1/2  [LED_603]  9.72,38.42 180 top
LED17.5  LED_CROSS1/2  [LED_603]  11.53,38.42 180 top
LED17.6  LED_CROSS1/2  [LED_603]  13.32,38.42 180 top
LED17.7  LED_CROSS1/2  [LED_603]  15.12,38.43 180 top
LED17.8  LED_CROSS1/2  [LED_603]  16.92,38.43 180 top
LED17.9  LED_CROSS1/2  [LED_603]  18.72,38.43 180 top
LED17.10  LED_CROSS1/2  [LED_603]  20.52,38.43 180 top
LED17.11  LED_CROSS1/2  [LED_603]  22.32,38.43 180 top
LED17.12  LED_CROSS1/2  [LED_603]  24.12,38.43 180 top
LED17.13  LED_CROSS1/2  [LED_603]  25.92,38.43 180 top
LED17.14  LED_CROSS1/2  [LED_603]  27.72,38.43 180 top
LED17.15  LED_CROSS1/2  [LED_603]  29.52,38.42 180 top
LED17.16  LED_CROSS1/2  [LED_603]  31.32,38.44 180 top
LED17.17  LED_CROSS1/2  [LED_603]  33.13,38.44 180 top
LED17.18  LED_CROSS1/2  [LED_603]  34.93,38.44 180 top
LED17.19  LED_CROSS1/2  [LED_603]  36.72,38.44 180 top
LED17.20  LED_CROSS1/2  [LED_603]  38.51,38.44 180 top
LED17.21  LED_CROSS1/2  [LED_603]  40.33,38.44 180 top
LED17.22  LED_CROSS1/2  [LED_603]  42.12,38.44 180 top
LED17.23  LED_CROSS1/2  [LED_603]  43.91,38.44 180 top
LED17.24  LED_CROSS1/2  [LED_603]  45.71,38.44 180 top
LED17.25  LED_CROSS1/2  [LED_603]  47.5,38.44 180 top
LED17.26  LED_CROSS1/2  [LED_603]  49.3,38.44 180 top
LED17.27  LED_CROSS1/2  [LED_603]  51.12,38.44 180 top
LED17.28  LED_CROSS1/2  [LED_603]  52.91,38.44 180 top
LED17.29  LED_CROSS1/2  [LED_603]  54.71,38.44 180 top
LED17.30  LED_CROSS1/2  [LED_603]  56.5,38.44 180 top
LED17.31  LED_CROSS1/2  [LED_603]  58.3,38.44 180 top
LED17.33  LED_CROSS1/2  [LED_603]  60.1,38.44 180 top
LED17.34  LED_CROSS1/2  [LED_603]  61.89,38.44 180 top
LED17.35  LED_CROSS1/2  [LED_603]  63.7,38.44 180 top
LED17.36  LED_CROSS1/2  [LED_603]  65.49,38.44 180 top
LED17.37  LED_CROSS1/2  [LED_603]  67.4,38.44 180 top
LED17.38  LED_CROSS1/2  [LED_603]  69.16,38.42 180 top
LED17.39  LED_CROSS1/2  [LED_603]  70.88,38.42 180 top
LED17.40  LED_CROSS1/2  [LED_603]  72.66,38.42 180 top
LED17.41  LED_CROSS1/2  [LED_603]  74.38,38.42 180 top
LED17.42  LED_CROSS1/2  [LED_603]  76.13,38.42 180 top
LED17.43  LED_CROSS1/2  [LED_603]  77.91,38.42 180 top
LED17.44  LED_CROSS1/2  [LED_603]  79.68,38.42 180 top
LED17.45  LED_CROSS1/2  [LED_603]  81.43,38.42 180 top
LED17.46  LED_CROSS1/2  [LED_603]  83.18,38.42 180 top
LED17.47  LED_CROSS1/2  [LED_603]  84.93,38.42 180 top
LED17.48  LED_CROSS1/2  [LED_603]  86.68,38.42 180 top
LED17.49  LED_CROSS1/2  [LED_603]  88.43,38.42 180 top
LED17.50  LED_CROSS1/2  [LED_603]  90.16,38.42 180 top
LED17.51  LED_CROSS1/2  [LED_603]  91.95,38.42 180 top
LED17.52  LED_CROSS1/2  [LED_603]  93.7,38.42 180 top
LED17.53  LED_CROSS1/2  [LED_603]  95.45,38.42 180 top
LED17.54  LED_CROSS1/2  [LED_603]  97.2,38.42 180 top
LED17.55  LED_CROSS1/2  [LED_603]  98.98,38.42 180 top
LED17.56  LED_CROSS1/2  [LED_603]  100.68,38.42 180 top
LED17.57  LED_CROSS1/2  [LED_603]  102.41,38.42 180 top
LED17.58  LED_CROSS1/2  [LED_603]  104.16,38.42 180 top
LED17.59  LED_CROSS1/2  [LED_603]  105.91,38.42 180 top
LED17.60  LED_CROSS1/2  [LED_603]  107.61,38.42 180 top
LED17.61  LED_CROSS1/2  [LED_603]  109.38,38.42 180 top
LED17.62  LED_CROSS1/2  [LED_603]  111.11,38.42 180 top
LED17.63  LED_CROSS1/2  [LED_603]  112.88,38.42 180 top
LED17.64  LED_CROSS1/2  [LED_603]  2.57,9.57 180 top
LED17.65  LED_CROSS1/2  [LED_603]  4.37,9.57 180 top
LED17.66  LED_CROSS1/2  [LED_603]  6.18,9.57 180 top
LED17.67  LED_CROSS1/2  [LED_603]  7.97,9.57 180 top
LED17.68  LED_CROSS1/2  [LED_603]  9.73,9.57 180 top
LED17.69  LED_CROSS1/2  [LED_603]  11.52,9.57 180 top
LED17.70  LED_CROSS1/2  [LED_603]  13.33,9.57 180 top
LED17.71  LED_CROSS1/2  [LED_603]  15.12,9.57 180 top
LED17.72  LED_CROSS1/2  [LED_603]  16.92,9.57 180 top
LED17.73  LED_CROSS1/2  [LED_603]  18.72,9.57 180 top
LED17.74  LED_CROSS1/2  [LED_603]  20.52,9.57 180 top
LED17.75  LED_CROSS1/2  [LED_603]  22.32,9.57 180 top
LED17.76  LED_CROSS1/2  [LED_603]  24.12,9.57 180 top
LED17.77  LED_CROSS1/2  [LED_603]  25.92,9.57 180 top
LED17.78  LED_CROSS1/2  [LED_603]  27.72,9.57 180 top
LED17.79  LED_CROSS1/2  [LED_603]  29.52,9.57 180 top
LED17.80  LED_CROSS1/2  [LED_603]  31.31,9.57 180 top
LED17.81  LED_CROSS1/2  [LED_603]  33.13,9.57 180 top
LED17.82  LED_CROSS1/2  [LED_603]  34.92,9.57 180 top
LED17.83  LED_CROSS1/2  [LED_603]  36.72,9.57 180 top
LED17.84  LED_CROSS1/2  [LED_603]  38.53,9.57 180 top
LED17.85  LED_CROSS1/2  [LED_603]  40.32,9.57 180 top
LED17.86  LED_CROSS1/2  [LED_603]  42.12,9.57 180 top
LED17.87  LED_CROSS1/2  [LED_603]  43.91,9.57 180 top
LED17.88  LED_CROSS1/2  [LED_603]  45.71,9.57 180 top
LED17.89  LED_CROSS1/2  [LED_603]  47.51,9.57 180 top
LED17.90  LED_CROSS1/2  [LED_603]  49.3,9.57 180 top
LED17.91  LED_CROSS1/2  [LED_603]  51.1,9.57 180 top
LED17.92  LED_CROSS1/2  [LED_603]  52.91,9.57 180 top
LED17.93  LED_CROSS1/2  [LED_603]  54.71,9.57 180 top
LED17.94  LED_CROSS1/2  [LED_603]  56.5,9.57 180 top
LED17.95  LED_CROSS1/2  [LED_603]  58.3,9.57 180 top
LED17.97  LED_CROSS1/2  [LED_603]  60.1,9.57 180 top
LED17.98  LED_CROSS1/2  [LED_603]  61.93,9.57 180 top
LED17.99  LED_CROSS1/2  [LED_603]  63.68,9.57 180 top
LED17.100  LED_CROSS1/2  [LED_603]  65.49,9.59 180 top
LED17.101  LED_CROSS1/2  [LED_603]  67.18,9.57 180 top
LED17.102  LED_CROSS1/2  [LED_603]  68.95,9.57 180 top
LED17.103  LED_CROSS1/2  [LED_603]  70.68,9.57 180 top
LED17.104  LED_CROSS1/2  [LED_603]  72.45,9.57 180 top
LED17.105  LED_CROSS1/2  [LED_603]  74.18,9.57 180 top
LED17.106  LED_CROSS1/2  [LED_603]  75.93,9.57 180 top
LED17.107  LED_CROSS1/2  [LED_603]  77.7,9.57 180 top
LED17.108  LED_CROSS1/2  [LED_603]  79.48,9.57 180 top
LED17.109  LED_CROSS1/2  [LED_603]  81.23,9.57 180 top
LED17.110  LED_CROSS1/2  [LED_603]  82.98,9.57 180 top
LED17.111  LED_CROSS1/2  [LED_603]  84.98,9.57 180 top
LED17.112  LED_CROSS1/2  [LED_603]  86.73,9.57 180 top
LED17.113  LED_CROSS1/2  [LED_603]  88.57,9.57 180 top
LED17.114  LED_CROSS1/2  [LED_603]  90.25,9.62 180 top
LED17.115  LED_CROSS1/2  [LED_603]  92,9.62 180 top
LED17.116  LED_CROSS1/2  [LED_603]  93.8,9.62 180 top
LED17.117  LED_CROSS1/2  [LED_603]  95.41,9.62 180 top
LED17.118  LED_CROSS1/2  [LED_603]  97.25,9.62 180 top
LED17.119  LED_CROSS1/2  [LED_603]  98.98,9.62 180 top
LED17.120  LED_CROSS1/2  [LED_603]  100.73,9.62 180 top
LED17.121  LED_CROSS1/2  [LED_603]  102.41,9.62 180 top
LED17.122  LED_CROSS1/2  [LED_603]  104.16,9.57 180 top
LED17.123  LED_CROSS1/2  [LED_603]  105.95,9.57 180 top
LED17.124  LED_CROSS1/2  [LED_603]  107.61,9.57 180 top
LED17.125  LED_CROSS1/2  [LED_603]  109.33,9.57 180 top
LED17.126  LED_CROSS1/2  [LED_603]  111.16,9.57 180 top
LED17.127  LED_CROSS1/2  [LED_603]  112.83,9.57 180 top
LED18.0  LED_CROSS1/2  [LED_603]  2.57,35.79 180 top
LED18.1  LED_CROSS1/2  [LED_603]  4.37,35.79 180 top
LED18.2  LED_CROSS1/2  [LED_603]  6.18,35.79 180 top
LED18.3  LED_CROSS1/2  [LED_603]  7.97,35.79 180 top
LED18.4  LED_CROSS1/2  [LED_603]  9.72,35.79 180 top
LED18.5  LED_CROSS1/2  [LED_603]  11.52,35.79 180 top
LED18.6  LED_CROSS1/2  [LED_603]  13.32,35.79 180 top
LED18.7  LED_CROSS1/2  [LED_603]  15.12,35.79 180 top
LED18.8  LED_CROSS1/2  [LED_603]  16.91,35.79 180 top
LED18.9  LED_CROSS1/2  [LED_603]  18.72,35.79 180 top
LED18.10  LED_CROSS1/2  [LED_603]  20.52,35.79 180 top
LED18.11  LED_CROSS1/2  [LED_603]  22.32,35.79 180 top
LED18.12  LED_CROSS1/2  [LED_603]  24.11,35.79 180 top
LED18.13  LED_CROSS1/2  [LED_603]  25.92,35.79 180 top
LED18.14  LED_CROSS1/2  [LED_603]  27.72,35.79 180 top
LED18.15  LED_CROSS1/2  [LED_603]  29.52,35.79 180 top
LED18.16  LED_CROSS1/2  [LED_603]  31.32,35.79 180 top
LED18.17  LED_CROSS1/2  [LED_603]  33.11,35.79 180 top
LED18.18  LED_CROSS1/2  [LED_603]  34.93,35.79 180 top
LED18.19  LED_CROSS1/2  [LED_603]  36.72,35.79 180 top
LED18.20  LED_CROSS1/2  [LED_603]  38.51,35.79 180 top
LED18.21  LED_CROSS1/2  [LED_603]  40.33,35.79 180 top
LED18.22  LED_CROSS1/2  [LED_603]  42.12,35.79 180 top
LED18.23  LED_CROSS1/2  [LED_603]  43.91,35.79 180 top
LED18.24  LED_CROSS1/2  [LED_603]  45.71,35.79 180 top
LED18.25  LED_CROSS1/2  [LED_603]  47.5,35.79 180 top
LED18.26  LED_CROSS1/2  [LED_603]  49.3,35.79 180 top
LED18.27  LED_CROSS1/2  [LED_603]  51.12,35.79 180 top
LED18.28  LED_CROSS1/2  [LED_603]  52.91,35.79 180 top
LED18.29  LED_CROSS1/2  [LED_603]  54.71,35.79 180 top
LED18.30  LED_CROSS1/2  [LED_603]  56.5,35.79 180 top
LED18.31  LED_CROSS1/2  [LED_603]  58.3,35.79 180 top
LED18.33  LED_CROSS1/2  [LED_603]  60.1,35.79 180 top
LED18.34  LED_CROSS1/2  [LED_603]  61.89,35.79 180 top
LED18.35  LED_CROSS1/2  [LED_603]  63.7,35.79 180 top
LED18.36  LED_CROSS1/2  [LED_603]  65.49,35.79 180 top
LED18.37  LED_CROSS1/2  [LED_603]  67.38,35.79 180 top
LED18.38  LED_CROSS1/2  [LED_603]  69.16,35.79 180 top
LED18.39  LED_CROSS1/2  [LED_603]  70.88,35.79 180 top
LED18.40  LED_CROSS1/2  [LED_603]  72.66,35.79 180 top
LED18.41  LED_CROSS1/2  [LED_603]  74.41,35.79 180 top
LED18.42  LED_CROSS1/2  [LED_603]  76.16,35.79 180 top
LED18.43  LED_CROSS1/2  [LED_603]  77.91,35.79 180 top
LED18.44  LED_CROSS1/2  [LED_603]  79.68,35.79 180 top
LED18.45  LED_CROSS1/2  [LED_603]  81.43,35.79 180 top
LED18.46  LED_CROSS1/2  [LED_603]  83.18,35.79 180 top
LED18.47  LED_CROSS1/2  [LED_603]  84.93,35.79 180 top
LED18.48  LED_CROSS1/2  [LED_603]  86.68,35.79 180 top
LED18.49  LED_CROSS1/2  [LED_603]  88.43,35.79 180 top
LED18.50  LED_CROSS1/2  [LED_603]  90.16,35.79 180 top
LED18.51  LED_CROSS1/2  [LED_603]  91.95,35.79 180 top
LED18.52  LED_CROSS1/2  [LED_603]  93.7,35.79 180 top
LED18.53  LED_CROSS1/2  [LED_603]  95.45,35.79 180 top
LED18.54  LED_CROSS1/2  [LED_603]  97.2,35.79 180 top
LED18.55  LED_CROSS1/2  [LED_603]  98.95,35.79 180 top
LED18.56  LED_CROSS1/2  [LED_603]  100.68,35.79 180 top
LED18.57  LED_CROSS1/2  [LED_603]  102.41,35.79 180 top
LED18.58  LED_CROSS1/2  [LED_603]  104.16,35.79 180 top
LED18.59  LED_CROSS1/2  [LED_603]  105.91,35.79 180 top
LED18.60  LED_CROSS1/2  [LED_603]  107.61,35.79 180 top
LED18.61  LED_CROSS1/2  [LED_603]  109.38,35.79 180 top
LED18.62  LED_CROSS1/2  [LED_603]  111.11,35.79 180 top
LED18.63  LED_CROSS1/2  [LED_603]  112.88,35.79 180 top
LED18.64  LED_CROSS1/2  [LED_603]  2.57,6.94 180 top
LED18.65  LED_CROSS1/2  [LED_603]  4.37,6.94 180 top
LED18.66  LED_CROSS1/2  [LED_603]  6.18,6.94 180 top
LED18.67  LED_CROSS1/2  [LED_603]  7.97,6.94 180 top
LED18.68  LED_CROSS1/2  [LED_603]  9.73,6.94 180 top
LED18.69  LED_CROSS1/2  [LED_603]  11.53,6.94 180 top
LED18.70  LED_CROSS1/2  [LED_603]  13.33,6.94 180 top
LED18.71  LED_CROSS1/2  [LED_603]  15.12,6.94 180 top
LED18.72  LED_CROSS1/2  [LED_603]  16.92,6.95 180 top
LED18.73  LED_CROSS1/2  [LED_603]  18.72,6.95 180 top
LED18.74  LED_CROSS1/2  [LED_603]  20.52,6.95 180 top
LED18.75  LED_CROSS1/2  [LED_603]  22.31,6.95 180 top
LED18.76  LED_CROSS1/2  [LED_603]  24.12,6.95 180 top
LED18.77  LED_CROSS1/2  [LED_603]  25.92,6.95 180 top
LED18.78  LED_CROSS1/2  [LED_603]  27.71,6.95 180 top
LED18.79  LED_CROSS1/2  [LED_603]  29.52,6.95 180 top
LED18.80  LED_CROSS1/2  [LED_603]  31.31,6.96 180 top
LED18.81  LED_CROSS1/2  [LED_603]  33.13,6.96 180 top
LED18.82  LED_CROSS1/2  [LED_603]  34.92,6.96 180 top
LED18.83  LED_CROSS1/2  [LED_603]  36.72,6.96 180 top
LED18.84  LED_CROSS1/2  [LED_603]  38.53,6.96 180 top
LED18.85  LED_CROSS1/2  [LED_603]  40.32,6.96 180 top
LED18.86  LED_CROSS1/2  [LED_603]  42.12,6.96 180 top
LED18.87  LED_CROSS1/2  [LED_603]  43.92,6.96 180 top
LED18.88  LED_CROSS1/2  [LED_603]  45.71,6.96 180 top
LED18.89  LED_CROSS1/2  [LED_603]  47.51,6.96 180 top
LED18.90  LED_CROSS1/2  [LED_603]  49.3,6.96 180 top
LED18.91  LED_CROSS1/2  [LED_603]  51.1,6.96 180 top
LED18.92  LED_CROSS1/2  [LED_603]  52.91,6.96 180 top
LED18.93  LED_CROSS1/2  [LED_603]  54.71,6.96 180 top
LED18.94  LED_CROSS1/2  [LED_603]  56.5,6.96 180 top
LED18.95  LED_CROSS1/2  [LED_603]  58.3,6.96 180 top
LED18.96  LED_CROSS1/2  [LED_603]  60.09,6.96 180 top
LED18.98  LED_CROSS1/2  [LED_603]  61.89,6.96 180 top
LED18.99  LED_CROSS1/2  [LED_603]  63.7,6.96 180 top
LED18.100  LED_CROSS1/2  [LED_603]  65.49,6.96 180 top
LED18.101  LED_CROSS1/2  [LED_603]  67.18,6.96 180 top
LED18.102  LED_CROSS1/2  [LED_603]  68.95,6.94 180 top
LED18.103  LED_CROSS1/2  [LED_603]  70.68,6.94 180 top
LED18.104  LED_CROSS1/2  [LED_603]  72.45,6.94 180 top
LED18.105  LED_CROSS1/2  [LED_603]  74.2,6.94 180 top
LED18.106  LED_CROSS1/2  [LED_603]  75.95,6.94 180 top
LED18.107  LED_CROSS1/2  [LED_603]  77.7,6.94 180 top
LED18.108  LED_CROSS1/2  [LED_603]  79.48,6.94 180 top
LED18.109  LED_CROSS1/2  [LED_603]  81.23,6.94 180 top
LED18.110  LED_CROSS1/2  [LED_603]  82.98,6.94 180 top
LED18.111  LED_CROSS1/2  [LED_603]  84.9,6.96 180 top
LED18.112  LED_CROSS1/2  [LED_603]  86.8,6.95 180 top
LED18.113  LED_CROSS1/2  [LED_603]  88.63,6.99 180 top
LED18.114  LED_CROSS1/2  [LED_603]  90.25,6.99 180 top
LED18.115  LED_CROSS1/2  [LED_603]  92,6.99 180 top
LED18.116  LED_CROSS1/2  [LED_603]  93.8,6.99 180 top
LED18.117  LED_CROSS1/2  [LED_603]  95.45,6.99 180 top
LED18.118  LED_CROSS1/2  [LED_603]  97.25,6.99 180 top
LED18.119  LED_CROSS1/2  [LED_603]  99,6.99 180 top
LED18.120  LED_CROSS1/2  [LED_603]  100.73,6.99 180 top
LED18.121  LED_CROSS1/2  [LED_603]  102.45,6.94 180 top
LED18.122  LED_CROSS1/2  [LED_603]  104.2,6.94 180 top
LED18.123  LED_CROSS1/2  [LED_603]  106,6.94 180 top
LED18.124  LED_CROSS1/2  [LED_603]  107.61,6.94 180 top
LED18.125  LED_CROSS1/2  [LED_603]  109.33,6.94 180 top
LED18.126  LED_CROSS1/2  [LED_603]  111.2,6.94 180 top
LED18.127  LED_CROSS1/2  [LED_603]  112.83,6.94 180 top
LED19.0  LED_CROSS1/2  [LED_603]  2.57,33.14 180 top
LED19.1  LED_CROSS1/2  [LED_603]  4.37,33.14 180 top
LED19.2  LED_CROSS1/2  [LED_603]  6.18,33.14 180 top
LED19.3  LED_CROSS1/2  [LED_603]  7.97,33.14 180 top
LED19.4  LED_CROSS1/2  [LED_603]  9.72,33.14 180 top
LED19.5  LED_CROSS1/2  [LED_603]  11.52,33.14 180 top
LED19.6  LED_CROSS1/2  [LED_603]  13.32,33.14 180 top
LED19.7  LED_CROSS1/2  [LED_603]  15.12,33.14 180 top
LED19.8  LED_CROSS1/2  [LED_603]  16.92,33.14 180 top
LED19.9  LED_CROSS1/2  [LED_603]  18.72,33.14 180 top
LED19.10  LED_CROSS1/2  [LED_603]  20.52,33.14 180 top
LED19.11  LED_CROSS1/2  [LED_603]  22.32,33.14 180 top
LED19.12  LED_CROSS1/2  [LED_603]  24.12,33.14 180 top
LED19.13  LED_CROSS1/2  [LED_603]  25.92,33.14 180 top
LED19.14  LED_CROSS1/2  [LED_603]  27.72,33.14 180 top
LED19.15  LED_CROSS1/2  [LED_603]  29.52,33.14 180 top
LED19.16  LED_CROSS1/2  [LED_603]  31.32,33.14 180 top
LED19.17  LED_CROSS1/2  [LED_603]  33.11,33.14 180 top
LED19.18  LED_CROSS1/2  [LED_603]  34.93,33.14 180 top
LED19.19  LED_CROSS1/2  [LED_603]  36.72,33.14 180 top
LED19.20  LED_CROSS1/2  [LED_603]  38.51,33.14 180 top
LED19.21  LED_CROSS1/2  [LED_603]  40.33,33.14 180 top
LED19.22  LED_CROSS1/2  [LED_603]  42.12,33.14 180 top
LED19.23  LED_CROSS1/2  [LED_603]  43.91,33.14 180 top
LED19.24  LED_CROSS1/2  [LED_603]  45.71,33.15 180 top
LED19.25  LED_CROSS1/2  [LED_603]  47.5,33.14 180 top
LED19.26  LED_CROSS1/2  [LED_603]  49.3,33.14 180 top
LED19.27  LED_CROSS1/2  [LED_603]  51.12,33.14 180 top
LED19.28  LED_CROSS1/2  [LED_603]  52.91,33.15 180 top
LED19.29  LED_CROSS1/2  [LED_603]  54.71,33.14 180 top
LED19.30  LED_CROSS1/2  [LED_603]  56.5,33.14 180 top
LED19.31  LED_CROSS1/2  [LED_603]  58.3,33.14 180 top
LED19.33  LED_CROSS1/2  [LED_603]  60.1,33.15 180 top
LED19.34  LED_CROSS1/2  [LED_603]  61.89,33.15 180 top
LED19.35  LED_CROSS1/2  [LED_603]  63.7,33.15 180 top
LED19.36  LED_CROSS1/2  [LED_603]  65.49,33.15 180 top
LED19.37  LED_CROSS1/2  [LED_603]  67.38,33.17 180 top
LED19.38  LED_CROSS1/2  [LED_603]  69.16,33.17 180 top
LED19.39  LED_CROSS1/2  [LED_603]  70.91,33.17 180 top
LED19.40  LED_CROSS1/2  [LED_603]  72.66,33.17 180 top
LED19.41  LED_CROSS1/2  [LED_603]  74.41,33.17 180 top
LED19.42  LED_CROSS1/2  [LED_603]  76.16,33.17 180 top
LED19.43  LED_CROSS1/2  [LED_603]  77.93,33.17 180 top
LED19.44  LED_CROSS1/2  [LED_603]  79.68,33.17 180 top
LED19.45  LED_CROSS1/2  [LED_603]  81.43,33.17 180 top
LED19.46  LED_CROSS1/2  [LED_603]  83.18,33.17 180 top
LED19.47  LED_CROSS1/2  [LED_603]  84.93,33.17 180 top
LED19.48  LED_CROSS1/2  [LED_603]  86.68,33.17 180 top
LED19.49  LED_CROSS1/2  [LED_603]  88.43,33.17 180 top
LED19.50  LED_CROSS1/2  [LED_603]  90.18,33.17 180 top
LED19.51  LED_CROSS1/2  [LED_603]  91.95,33.17 180 top
LED19.52  LED_CROSS1/2  [LED_603]  93.7,33.17 180 top
LED19.53  LED_CROSS1/2  [LED_603]  95.45,33.17 180 top
LED19.54  LED_CROSS1/2  [LED_603]  97.2,33.17 180 top
LED19.55  LED_CROSS1/2  [LED_603]  98.95,33.17 180 top
LED19.56  LED_CROSS1/2  [LED_603]  100.68,33.17 180 top
LED19.57  LED_CROSS1/2  [LED_603]  102.41,33.17 180 top
LED19.58  LED_CROSS1/2  [LED_603]  104.16,33.17 180 top
LED19.59  LED_CROSS1/2  [LED_603]  105.91,33.17 180 top
LED19.60  LED_CROSS1/2  [LED_603]  107.63,33.17 180 top
LED19.61  LED_CROSS1/2  [LED_603]  109.41,33.17 180 top
LED19.62  LED_CROSS1/2  [LED_603]  111.13,33.17 180 top
LED19.63  LED_CROSS1/2  [LED_603]  112.91,33.17 180 top
LED19.64  LED_CROSS1/2  [LED_603]  2.57,4.29 180 top
LED19.65  LED_CROSS1/2  [LED_603]  4.37,4.29 180 top
LED19.66  LED_CROSS1/2  [LED_603]  6.18,4.29 180 top
LED19.67  LED_CROSS1/2  [LED_603]  7.97,4.29 180 top
LED19.68  LED_CROSS1/2  [LED_603]  9.73,4.29 180 top
LED19.69  LED_CROSS1/2  [LED_603]  11.52,4.29 180 top
LED19.70  LED_CROSS1/2  [LED_603]  13.32,4.29 180 top
LED19.71  LED_CROSS1/2  [LED_603]  14.86,4.29 180 top
LED19.72  LED_CROSS1/2  [LED_603]  16.92,4.29 180 top
LED19.73  LED_CROSS1/2  [LED_603]  18.72,4.29 180 top
LED19.74  LED_CROSS1/2  [LED_603]  20.52,4.29 180 top
LED19.75  LED_CROSS1/2  [LED_603]  22.32,4.29 180 top
LED19.76  LED_CROSS1/2  [LED_603]  24.11,4.29 180 top
LED19.77  LED_CROSS1/2  [LED_603]  25.92,4.29 180 top
LED19.78  LED_CROSS1/2  [LED_603]  27.71,4.29 180 top
LED19.79  LED_CROSS1/2  [LED_603]  29.52,4.29 180 top
LED19.80  LED_CROSS1/2  [LED_603]  31.31,4.27 180 top
LED19.81  LED_CROSS1/2  [LED_603]  33.13,4.27 180 top
LED19.82  LED_CROSS1/2  [LED_603]  34.92,4.27 180 top
LED19.83  LED_CROSS1/2  [LED_603]  36.72,4.27 180 top
LED19.84  LED_CROSS1/2  [LED_603]  38.53,4.27 180 top
LED19.85  LED_CROSS1/2  [LED_603]  40.32,4.27 180 top
LED19.86  LED_CROSS1/2  [LED_603]  42.12,4.27 180 top
LED19.87  LED_CROSS1/2  [LED_603]  43.92,4.27 180 top
LED19.88  LED_CROSS1/2  [LED_603]  45.71,4.27 180 top
LED19.89  LED_CROSS1/2  [LED_603]  47.51,4.27 180 top
LED19.90  LED_CROSS1/2  [LED_603]  49.3,4.27 180 top
LED19.91  LED_CROSS1/2  [LED_603]  51.1,4.27 180 top
LED19.92  LED_CROSS1/2  [LED_603]  52.91,4.27 180 top
LED19.93  LED_CROSS1/2  [LED_603]  54.71,4.27 180 top
LED19.94  LED_CROSS1/2  [LED_603]  56.5,4.27 180 top
LED19.96  LED_CROSS1/2  [LED_603]  58.3,4.27 180 top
